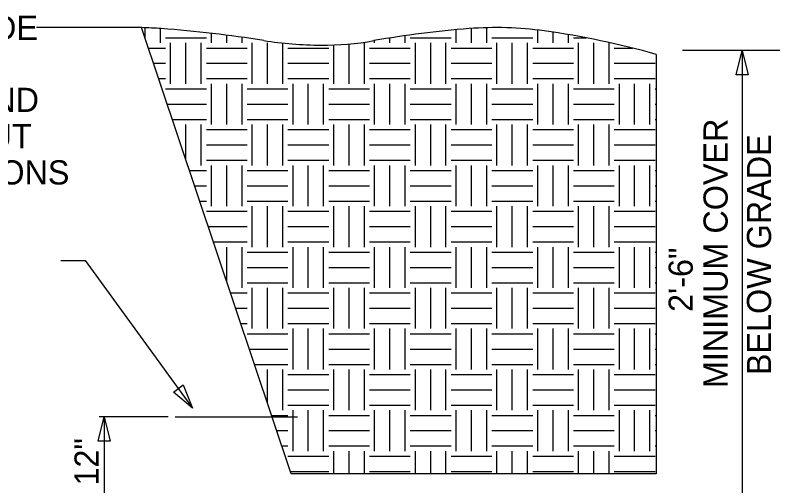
# Model space of a CAD drawing. Extents: x -12315.1 to -12267.3, y -12275 to -12184.8.
# Drawn here: x -12288.43 to -12267.35, y -12197.77 to -12184.81 of the extents above; entities that cross this region are included whole.
import ezdxf

# ---------------------------------------------------------------- set-up
doc = ezdxf.new("R2010")
doc.units = 0
for name, color, linetype in [('G-ANNO-TEXT', 7, 'Continuous'), ('G-DETL-LINE', 7, 'Continuous'), ('G-DETL-PATT', 7, 'Continuous')]:
    doc.layers.add(name, color=color, linetype=linetype)

msp = doc.modelspace()

# ---------------------------------------------------------------- linework, layer by layer
at = {"layer": 'G-ANNO-TEXT'}
for p, q in [((-12284.948, -12185.147), (-12287.843, -12185.147)), ((-12270.031, -12185.766), (-12267.346, -12185.766)), ((-12268.379, -12185.78), (-12268.379, -12199.257)), ((-12287.171, -12191.568), (-12286.504, -12191.568)), ((-12286.504, -12191.568), (-12283.54, -12195.634)), ((-12284.216, -12195.878), (-12286.118, -12195.878)), ((-12285.975, -12195.878), (-12285.975, -12199.291))]:
    msp.add_line(p, q, dxfattribs=at)
for points in [[(-12268.545, -12186.447), (-12268.379, -12185.78), (-12268.212, -12186.447)], [(-12283.798, -12194.997), (-12283.54, -12195.634), (-12284.067, -12195.193)], [(-12286.141, -12196.545), (-12285.975, -12195.878), (-12285.808, -12196.545)]]:
    msp.add_lwpolyline(points, close=True, dxfattribs=at)
at = {"layer": 'G-DETL-LINE'}
for p, q in [((-12280.823, -12197.442), (-12284.948, -12185.147)), ((-12270.751, -12185.884), (-12270.751, -12197.442)), ((-12270.751, -12197.442), (-12280.823, -12197.442))]:
    msp.add_line(p, q, dxfattribs=at)
for centre, radius, start, end in [((-12285.272, -12197.103), 11.96, 85.8256, 88.4429), ((-12286.828, -12218.429), 33.343, 80.9379, 85.8263), ((-12273.898, -12211.649), 26.551, 94.3454, 100.0626), ((-12275.172, -12194.879), 9.733, 82.1646, 94.3457), ((-12276.956, -12207.838), 22.814, 74.2168, 82.1645), ((-12279.945, -12175.273), 10.358, 260.9379, 269.7145), ((-12279.956, -12177.511), 8.12, 269.7145, 280.0628)]:
    msp.add_arc(centre, radius, start, end, dxfattribs=at)
at = {"layer": 'G-DETL-PATT'}
for p, q in [((-12284.847, -12185.448), (-12284.847, -12185.15)), ((-12284.847, -12185.448), (-12284.847, -12185.15)), ((-12284.425, -12185.569), (-12284.425, -12185.172)), ((-12276.268, -12185.569), (-12276.268, -12185.203)), ((-12275.847, -12185.569), (-12275.847, -12185.169)), ((-12275.425, -12185.569), (-12275.425, -12185.149)), ((-12274.018, -12185.569), (-12274.018, -12185.214)), ((-12284.284, -12185.428), (-12283.159, -12185.428)), ((-12283.018, -12185.569), (-12283.018, -12185.304)), ((-12282.597, -12185.569), (-12282.597, -12185.355)), ((-12282.175, -12185.569), (-12282.175, -12185.412)), ((-12278.097, -12185.569), (-12278.097, -12185.431)), ((-12277.675, -12185.569), (-12277.675, -12185.367)), ((-12277.534, -12185.428), (-12276.409, -12185.428)), ((-12275.284, -12185.428), (-12274.159, -12185.428)), ((-12273.597, -12185.569), (-12273.597, -12185.272)), ((-12273.175, -12185.569), (-12273.175, -12185.339)), ((-12273.034, -12185.428), (-12272.679, -12185.428)), ((-12284.143, -12186.694), (-12284.143, -12185.569)), ((-12283.722, -12186.694), (-12283.722, -12185.569)), ((-12283.3, -12186.694), (-12283.3, -12185.569)), ((-12281.893, -12186.694), (-12281.893, -12185.569)), ((-12281.472, -12186.694), (-12281.472, -12185.569)), ((-12281.05, -12186.694), (-12281.05, -12185.572)), ((-12279.643, -12186.694), (-12279.643, -12185.625)), ((-12279.222, -12186.694), (-12279.222, -12185.597)), ((-12278.8, -12186.694), (-12278.8, -12185.569)), ((-12278.518, -12185.569), (-12278.518, -12185.502)), ((-12277.393, -12186.694), (-12277.393, -12185.569)), ((-12276.972, -12186.694), (-12276.972, -12185.569)), ((-12276.55, -12186.694), (-12276.55, -12185.569)), ((-12275.143, -12186.694), (-12275.143, -12185.569)), ((-12274.722, -12186.694), (-12274.722, -12185.569)), ((-12274.3, -12186.694), (-12274.3, -12185.569)), ((-12272.893, -12186.694), (-12272.893, -12185.569)), ((-12272.472, -12186.694), (-12272.472, -12185.569)), ((-12272.05, -12186.694), (-12272.05, -12185.569)), ((-12284.759, -12185.709), (-12284.284, -12185.709)), ((-12283.159, -12185.709), (-12282.034, -12185.709)), ((-12280.909, -12185.709), (-12279.784, -12185.709)), ((-12278.659, -12185.709), (-12277.534, -12185.709)), ((-12276.409, -12185.709), (-12275.284, -12185.709)), ((-12274.159, -12185.709), (-12273.034, -12185.709)), ((-12271.909, -12185.709), (-12271.405, -12185.709)), ((-12284.617, -12186.131), (-12284.284, -12186.131)), ((-12283.159, -12186.131), (-12282.034, -12186.131)), ((-12280.909, -12186.131), (-12279.784, -12186.131)), ((-12278.659, -12186.131), (-12277.534, -12186.131)), ((-12276.409, -12186.131), (-12275.284, -12186.131)), ((-12274.159, -12186.131), (-12273.034, -12186.131)), ((-12271.909, -12186.131), (-12270.784, -12186.131)), ((-12284.476, -12186.553), (-12284.284, -12186.553)), ((-12284.425, -12186.706), (-12284.425, -12186.694)), ((-12283.159, -12186.553), (-12282.034, -12186.553)), ((-12283.018, -12187.819), (-12283.018, -12186.694)), ((-12282.597, -12187.819), (-12282.597, -12186.694)), ((-12282.175, -12187.819), (-12282.175, -12186.694)), ((-12280.909, -12186.553), (-12279.784, -12186.553)), ((-12280.768, -12187.819), (-12280.768, -12186.694)), ((-12280.768, -12187.819), (-12280.768, -12186.694)), ((-12280.347, -12187.819), (-12280.347, -12186.694)), ((-12279.925, -12187.819), (-12279.925, -12186.694)), ((-12278.659, -12186.553), (-12277.534, -12186.553)), ((-12278.518, -12187.819), (-12278.518, -12186.694)), ((-12278.097, -12187.819), (-12278.097, -12186.694)), ((-12277.675, -12187.819), (-12277.675, -12186.694)), ((-12276.409, -12186.553), (-12275.284, -12186.553)), ((-12276.268, -12187.819), (-12276.268, -12186.694)), ((-12275.847, -12187.819), (-12275.847, -12186.694)), ((-12275.425, -12187.819), (-12275.425, -12186.694)), ((-12274.159, -12186.553), (-12273.034, -12186.553)), ((-12274.018, -12187.819), (-12274.018, -12186.694)), ((-12273.597, -12187.819), (-12273.597, -12186.694)), ((-12273.175, -12187.819), (-12273.175, -12186.694)), ((-12271.909, -12186.553), (-12270.784, -12186.553)), ((-12271.768, -12187.819), (-12271.768, -12186.694)), ((-12271.347, -12187.819), (-12271.347, -12186.694)), ((-12270.925, -12187.819), (-12270.925, -12186.694)), ((-12284.284, -12186.834), (-12283.159, -12186.834)), ((-12282.034, -12186.834), (-12280.909, -12186.834)), ((-12279.784, -12186.834), (-12278.659, -12186.834)), ((-12277.534, -12186.834), (-12276.409, -12186.834)), ((-12275.284, -12186.834), (-12274.159, -12186.834)), ((-12273.034, -12186.834), (-12271.909, -12186.834)), ((-12270.784, -12186.834), (-12270.751, -12186.834)), ((-12284.24, -12187.256), (-12283.159, -12187.256)), ((-12282.034, -12187.256), (-12280.909, -12187.256)), ((-12279.784, -12187.256), (-12278.659, -12187.256)), ((-12277.534, -12187.256), (-12276.409, -12187.256)), ((-12275.284, -12187.256), (-12274.159, -12187.256)), ((-12273.034, -12187.256), (-12271.909, -12187.256)), ((-12270.784, -12187.256), (-12270.751, -12187.256)), ((-12284.098, -12187.678), (-12283.159, -12187.678)), ((-12282.034, -12187.678), (-12280.909, -12187.678)), ((-12279.784, -12187.678), (-12278.659, -12187.678)), ((-12277.534, -12187.678), (-12276.409, -12187.678)), ((-12275.284, -12187.678), (-12274.159, -12187.678)), ((-12273.034, -12187.678), (-12271.909, -12187.678)), ((-12270.784, -12187.678), (-12270.751, -12187.678)), ((-12283.722, -12188.801), (-12283.722, -12187.819)), ((-12283.3, -12188.944), (-12283.3, -12187.819)), ((-12283.159, -12187.959), (-12282.034, -12187.959)), ((-12281.893, -12188.944), (-12281.893, -12187.819)), ((-12281.472, -12188.944), (-12281.472, -12187.819)), ((-12281.05, -12188.944), (-12281.05, -12187.819)), ((-12280.909, -12187.959), (-12279.784, -12187.959)), ((-12279.643, -12188.944), (-12279.643, -12187.819)), ((-12279.222, -12188.944), (-12279.222, -12187.819)), ((-12278.8, -12188.944), (-12278.8, -12187.819)), ((-12278.659, -12187.959), (-12277.534, -12187.959)), ((-12277.393, -12188.944), (-12277.393, -12187.819)), ((-12276.972, -12188.944), (-12276.972, -12187.819)), ((-12276.55, -12188.944), (-12276.55, -12187.819)), ((-12276.409, -12187.959), (-12275.284, -12187.959)), ((-12275.143, -12188.944), (-12275.143, -12187.819)), ((-12274.722, -12188.944), (-12274.722, -12187.819)), ((-12274.3, -12188.944), (-12274.3, -12187.819)), ((-12274.159, -12187.959), (-12273.034, -12187.959)), ((-12272.893, -12188.944), (-12272.893, -12187.819)), ((-12272.472, -12188.944), (-12272.472, -12187.819)), ((-12272.05, -12188.944), (-12272.05, -12187.819)), ((-12271.909, -12187.959), (-12270.784, -12187.959)), ((-12283.159, -12188.381), (-12282.034, -12188.381)), ((-12280.909, -12188.381), (-12279.784, -12188.381)), ((-12278.659, -12188.381), (-12277.534, -12188.381)), ((-12276.409, -12188.381), (-12275.284, -12188.381)), ((-12274.159, -12188.381), (-12273.034, -12188.381)), ((-12271.909, -12188.381), (-12270.784, -12188.381)), ((-12283.159, -12188.803), (-12282.034, -12188.803)), ((-12280.909, -12188.803), (-12279.784, -12188.803)), ((-12278.659, -12188.803), (-12277.534, -12188.803)), ((-12276.409, -12188.803), (-12275.284, -12188.803)), ((-12274.159, -12188.803), (-12273.034, -12188.803)), ((-12271.909, -12188.803), (-12270.784, -12188.803)), ((-12283.018, -12190.069), (-12283.018, -12188.944)), ((-12282.597, -12190.069), (-12282.597, -12188.944)), ((-12282.175, -12190.069), (-12282.175, -12188.944)), ((-12280.768, -12190.069), (-12280.768, -12188.944)), ((-12280.347, -12190.069), (-12280.347, -12188.944)), ((-12279.925, -12190.069), (-12279.925, -12188.944)), ((-12278.518, -12190.069), (-12278.518, -12188.944)), ((-12278.097, -12190.069), (-12278.097, -12188.944)), ((-12277.675, -12190.069), (-12277.675, -12188.944)), ((-12276.268, -12190.069), (-12276.268, -12188.944)), ((-12275.847, -12190.069), (-12275.847, -12188.944)), ((-12275.425, -12190.069), (-12275.425, -12188.944)), ((-12274.018, -12190.069), (-12274.018, -12188.944)), ((-12273.597, -12190.069), (-12273.597, -12188.944)), ((-12273.175, -12190.069), (-12273.175, -12188.944)), ((-12271.768, -12190.069), (-12271.768, -12188.944)), ((-12271.347, -12190.069), (-12271.347, -12188.944)), ((-12270.925, -12190.069), (-12270.925, -12188.944)), ((-12283.627, -12189.084), (-12283.159, -12189.084)), ((-12282.034, -12189.084), (-12280.909, -12189.084)), ((-12279.784, -12189.084), (-12278.659, -12189.084)), ((-12277.534, -12189.084), (-12276.409, -12189.084)), ((-12275.284, -12189.084), (-12274.159, -12189.084)), ((-12273.034, -12189.084), (-12271.909, -12189.084)), ((-12270.784, -12189.084), (-12270.751, -12189.084)), ((-12283.485, -12189.506), (-12283.159, -12189.506)), ((-12282.034, -12189.506), (-12280.909, -12189.506)), ((-12279.784, -12189.506), (-12278.659, -12189.506)), ((-12277.534, -12189.506), (-12276.409, -12189.506)), ((-12275.284, -12189.506), (-12274.159, -12189.506)), ((-12273.034, -12189.506), (-12271.909, -12189.506)), ((-12270.784, -12189.506), (-12270.751, -12189.506)), ((-12283.344, -12189.928), (-12283.159, -12189.928)), ((-12282.034, -12189.928), (-12280.909, -12189.928)), ((-12281.893, -12191.194), (-12281.893, -12190.069)), ((-12281.472, -12191.194), (-12281.472, -12190.069)), ((-12281.05, -12191.194), (-12281.05, -12190.069)), ((-12279.784, -12189.928), (-12278.659, -12189.928)), ((-12279.643, -12191.194), (-12279.643, -12190.069)), ((-12279.222, -12191.194), (-12279.222, -12190.069)), ((-12278.8, -12191.194), (-12278.8, -12190.069)), ((-12277.534, -12189.928), (-12276.409, -12189.928)), ((-12277.393, -12191.194), (-12277.393, -12190.069)), ((-12276.972, -12191.194), (-12276.972, -12190.069)), ((-12276.55, -12191.194), (-12276.55, -12190.069)), ((-12275.284, -12189.928), (-12274.159, -12189.928)), ((-12275.143, -12191.194), (-12275.143, -12190.069)), ((-12274.722, -12191.194), (-12274.722, -12190.069)), ((-12274.3, -12191.194), (-12274.3, -12190.069)), ((-12273.034, -12189.928), (-12271.909, -12189.928)), ((-12272.893, -12191.194), (-12272.893, -12190.069)), ((-12272.472, -12191.194), (-12272.472, -12190.069)), ((-12272.05, -12191.194), (-12272.05, -12190.069)), ((-12270.784, -12189.928), (-12270.751, -12189.928)), ((-12283.159, -12190.209), (-12282.034, -12190.209)), ((-12280.909, -12190.209), (-12279.784, -12190.209)), ((-12278.659, -12190.209), (-12277.534, -12190.209)), ((-12276.409, -12190.209), (-12275.284, -12190.209)), ((-12274.159, -12190.209), (-12273.034, -12190.209)), ((-12271.909, -12190.209), (-12270.784, -12190.209)), ((-12271.909, -12190.209), (-12270.784, -12190.209)), ((-12283.108, -12190.631), (-12282.034, -12190.631)), ((-12283.108, -12190.631), (-12282.034, -12190.631)), ((-12280.909, -12190.631), (-12279.784, -12190.631)), ((-12278.659, -12190.631), (-12277.534, -12190.631)), ((-12276.409, -12190.631), (-12275.284, -12190.631)), ((-12274.159, -12190.631), (-12273.034, -12190.631)), ((-12271.909, -12190.631), (-12270.784, -12190.631)), ((-12282.966, -12191.053), (-12282.034, -12191.053)), ((-12280.909, -12191.053), (-12279.784, -12191.053)), ((-12278.659, -12191.053), (-12277.534, -12191.053)), ((-12276.409, -12191.053), (-12275.284, -12191.053)), ((-12274.159, -12191.053), (-12273.034, -12191.053)), ((-12271.909, -12191.053), (-12270.784, -12191.053)), ((-12282.597, -12192.155), (-12282.597, -12191.194)), ((-12282.175, -12192.319), (-12282.175, -12191.194)), ((-12282.034, -12191.334), (-12280.909, -12191.334)), ((-12280.768, -12192.319), (-12280.768, -12191.194)), ((-12280.347, -12192.319), (-12280.347, -12191.194)), ((-12279.925, -12192.319), (-12279.925, -12191.194)), ((-12279.784, -12191.334), (-12278.659, -12191.334)), ((-12278.518, -12192.319), (-12278.518, -12191.194)), ((-12278.097, -12192.319), (-12278.097, -12191.194)), ((-12277.675, -12192.319), (-12277.675, -12191.194)), ((-12277.534, -12191.334), (-12276.409, -12191.334)), ((-12276.268, -12192.319), (-12276.268, -12191.194)), ((-12275.847, -12192.319), (-12275.847, -12191.194)), ((-12275.425, -12192.319), (-12275.425, -12191.194)), ((-12275.284, -12191.334), (-12274.159, -12191.334)), ((-12274.018, -12192.319), (-12274.018, -12191.194)), ((-12273.597, -12192.319), (-12273.597, -12191.194)), ((-12273.175, -12192.319), (-12273.175, -12191.194)), ((-12273.034, -12191.334), (-12271.909, -12191.334)), ((-12271.768, -12192.319), (-12271.768, -12191.194)), ((-12271.347, -12192.319), (-12271.347, -12191.194)), ((-12270.925, -12192.319), (-12270.925, -12191.194)), ((-12270.784, -12191.334), (-12270.751, -12191.334)), ((-12282.034, -12191.756), (-12280.909, -12191.756)), ((-12279.784, -12191.756), (-12278.659, -12191.756)), ((-12277.534, -12191.756), (-12276.409, -12191.756)), ((-12275.284, -12191.756), (-12274.159, -12191.756)), ((-12273.034, -12191.756), (-12271.909, -12191.756)), ((-12270.784, -12191.756), (-12270.751, -12191.756)), ((-12282.034, -12192.178), (-12280.909, -12192.178)), ((-12279.784, -12192.178), (-12278.659, -12192.178)), ((-12277.534, -12192.178), (-12276.409, -12192.178)), ((-12275.284, -12192.178), (-12274.159, -12192.178)), ((-12273.034, -12192.178), (-12271.909, -12192.178)), ((-12270.784, -12192.178), (-12270.751, -12192.178)), ((-12281.893, -12193.444), (-12281.893, -12192.319)), ((-12281.472, -12193.444), (-12281.472, -12192.319)), ((-12281.05, -12193.444), (-12281.05, -12192.319)), ((-12279.643, -12193.444), (-12279.643, -12192.319)), ((-12279.222, -12193.444), (-12279.222, -12192.319)), ((-12278.8, -12193.444), (-12278.8, -12192.319)), ((-12277.393, -12193.444), (-12277.393, -12192.319)), ((-12276.972, -12193.444), (-12276.972, -12192.319)), ((-12276.55, -12193.444), (-12276.55, -12192.319)), ((-12275.143, -12193.444), (-12275.143, -12192.319)), ((-12274.722, -12193.444), (-12274.722, -12192.319)), ((-12274.3, -12193.444), (-12274.3, -12192.319)), ((-12272.893, -12193.444), (-12272.893, -12192.319)), ((-12272.472, -12193.444), (-12272.472, -12192.319)), ((-12272.05, -12193.444), (-12272.05, -12192.319)), ((-12282.494, -12192.459), (-12282.034, -12192.459)), ((-12280.909, -12192.459), (-12279.784, -12192.459)), ((-12278.659, -12192.459), (-12277.534, -12192.459)), ((-12276.409, -12192.459), (-12275.284, -12192.459)), ((-12274.159, -12192.459), (-12273.034, -12192.459)), ((-12271.909, -12192.459), (-12270.784, -12192.459)), ((-12282.353, -12192.881), (-12282.034, -12192.881)), ((-12280.909, -12192.881), (-12279.784, -12192.881)), ((-12278.659, -12192.881), (-12277.534, -12192.881)), ((-12276.409, -12192.881), (-12275.284, -12192.881)), ((-12274.159, -12192.881), (-12273.034, -12192.881)), ((-12271.909, -12192.881), (-12270.784, -12192.881)), ((-12282.211, -12193.303), (-12282.034, -12193.303)), ((-12280.909, -12193.303), (-12279.784, -12193.303)), ((-12280.768, -12194.569), (-12280.768, -12193.444)), ((-12280.347, -12194.569), (-12280.347, -12193.444)), ((-12279.925, -12194.569), (-12279.925, -12193.444)), ((-12278.659, -12193.303), (-12277.534, -12193.303)), ((-12278.518, -12194.569), (-12278.518, -12193.444)), ((-12278.097, -12194.569), (-12278.097, -12193.444)), ((-12277.675, -12194.569), (-12277.675, -12193.444)), ((-12276.409, -12193.303), (-12275.284, -12193.303)), ((-12276.268, -12194.569), (-12276.268, -12193.444)), ((-12275.847, -12194.569), (-12275.847, -12193.444)), ((-12275.425, -12194.569), (-12275.425, -12193.444)), ((-12274.159, -12193.303), (-12273.034, -12193.303)), ((-12274.018, -12194.569), (-12274.018, -12193.444)), ((-12273.597, -12194.569), (-12273.597, -12193.444)), ((-12273.175, -12194.569), (-12273.175, -12193.444)), ((-12271.909, -12193.303), (-12270.784, -12193.303)), ((-12271.768, -12194.569), (-12271.768, -12193.444)), ((-12271.347, -12194.569), (-12271.347, -12193.444)), ((-12270.925, -12194.569), (-12270.925, -12193.444)), ((-12282.034, -12193.584), (-12280.909, -12193.584)), ((-12279.784, -12193.584), (-12278.659, -12193.584)), ((-12277.534, -12193.584), (-12276.409, -12193.584)), ((-12275.284, -12193.584), (-12274.159, -12193.584)), ((-12273.034, -12193.584), (-12271.909, -12193.584)), ((-12270.784, -12193.584), (-12270.751, -12193.584)), ((-12281.975, -12194.006), (-12280.909, -12194.006)), ((-12279.784, -12194.006), (-12278.659, -12194.006)), ((-12277.534, -12194.006), (-12276.409, -12194.006)), ((-12275.284, -12194.006), (-12274.159, -12194.006)), ((-12273.034, -12194.006), (-12271.909, -12194.006)), ((-12270.784, -12194.006), (-12270.751, -12194.006)), ((-12281.834, -12194.428), (-12280.909, -12194.428)), ((-12279.784, -12194.428), (-12278.659, -12194.428)), ((-12277.534, -12194.428), (-12276.409, -12194.428)), ((-12275.284, -12194.428), (-12274.159, -12194.428)), ((-12273.034, -12194.428), (-12271.909, -12194.428)), ((-12270.784, -12194.428), (-12270.751, -12194.428)), ((-12281.472, -12195.508), (-12281.472, -12194.569)), ((-12281.05, -12195.694), (-12281.05, -12194.569)), ((-12280.909, -12194.709), (-12279.784, -12194.709)), ((-12279.643, -12195.694), (-12279.643, -12194.569)), ((-12279.222, -12195.694), (-12279.222, -12194.569)), ((-12278.8, -12195.694), (-12278.8, -12194.569)), ((-12278.659, -12194.709), (-12277.534, -12194.709)), ((-12277.393, -12195.694), (-12277.393, -12194.569)), ((-12276.972, -12195.694), (-12276.972, -12194.569)), ((-12276.55, -12195.694), (-12276.55, -12194.569)), ((-12276.409, -12194.709), (-12275.284, -12194.709)), ((-12275.143, -12195.694), (-12275.143, -12194.569)), ((-12274.722, -12195.694), (-12274.722, -12194.569)), ((-12274.3, -12195.694), (-12274.3, -12194.569)), ((-12274.159, -12194.709), (-12273.034, -12194.709)), ((-12272.893, -12195.694), (-12272.893, -12194.569)), ((-12272.472, -12195.694), (-12272.472, -12194.569)), ((-12272.05, -12195.694), (-12272.05, -12194.569)), ((-12271.909, -12194.709), (-12270.784, -12194.709)), ((-12280.909, -12195.131), (-12279.784, -12195.131)), ((-12278.659, -12195.131), (-12277.534, -12195.131)), ((-12276.409, -12195.131), (-12275.284, -12195.131)), ((-12274.159, -12195.131), (-12273.034, -12195.131)), ((-12271.909, -12195.131), (-12270.784, -12195.131)), ((-12280.909, -12195.553), (-12279.784, -12195.553)), ((-12280.768, -12196.819), (-12280.768, -12195.694)), ((-12280.347, -12196.819), (-12280.347, -12195.694)), ((-12279.925, -12196.819), (-12279.925, -12195.694)), ((-12278.659, -12195.553), (-12277.534, -12195.553)), ((-12278.518, -12196.819), (-12278.518, -12195.694)), ((-12278.097, -12196.819), (-12278.097, -12195.694)), ((-12277.675, -12196.819), (-12277.675, -12195.694)), ((-12276.409, -12195.553), (-12275.284, -12195.553)), ((-12276.268, -12196.819), (-12276.268, -12195.694)), ((-12275.847, -12196.819), (-12275.847, -12195.694)), ((-12275.425, -12196.819), (-12275.425, -12195.694)), ((-12275.425, -12196.819), (-12275.425, -12195.694)), ((-12274.159, -12195.553), (-12273.034, -12195.553)), ((-12274.018, -12196.819), (-12274.018, -12195.694)), ((-12273.597, -12196.819), (-12273.597, -12195.694)), ((-12273.175, -12196.819), (-12273.175, -12195.694)), ((-12271.909, -12195.553), (-12270.784, -12195.553)), ((-12271.768, -12196.819), (-12271.768, -12195.694)), ((-12271.347, -12196.819), (-12271.347, -12195.694)), ((-12270.925, -12196.819), (-12270.925, -12195.694)), ((-12284.023, -12195.878), (-12280.648, -12195.878)), ((-12281.362, -12195.834), (-12280.909, -12195.834)), ((-12279.784, -12195.834), (-12278.659, -12195.834)), ((-12277.534, -12195.834), (-12276.409, -12195.834)), ((-12275.284, -12195.834), (-12274.159, -12195.834)), ((-12273.034, -12195.834), (-12271.909, -12195.834)), ((-12270.784, -12195.834), (-12270.751, -12195.834)), ((-12281.221, -12196.256), (-12280.909, -12196.256)), ((-12279.784, -12196.256), (-12278.659, -12196.256)), ((-12277.534, -12196.256), (-12276.409, -12196.256)), ((-12275.284, -12196.256), (-12274.159, -12196.256)), ((-12273.034, -12196.256), (-12271.909, -12196.256)), ((-12270.784, -12196.256), (-12270.751, -12196.256)), ((-12281.079, -12196.678), (-12280.909, -12196.678)), ((-12279.784, -12196.678), (-12278.659, -12196.678)), ((-12277.534, -12196.678), (-12276.409, -12196.678)), ((-12275.284, -12196.678), (-12274.159, -12196.678)), ((-12273.034, -12196.678), (-12271.909, -12196.678)), ((-12270.784, -12196.678), (-12270.751, -12196.678)), ((-12280.909, -12196.959), (-12279.784, -12196.959)), ((-12279.643, -12197.441), (-12279.643, -12196.819)), ((-12279.222, -12197.441), (-12279.222, -12196.819)), ((-12278.8, -12197.441), (-12278.8, -12196.819)), ((-12278.659, -12196.959), (-12277.534, -12196.959)), ((-12277.393, -12197.441), (-12277.393, -12196.819)), ((-12276.972, -12197.441), (-12276.972, -12196.819)), ((-12276.55, -12197.441), (-12276.55, -12196.819)), ((-12276.409, -12196.959), (-12275.284, -12196.959)), ((-12275.143, -12197.441), (-12275.143, -12196.819)), ((-12274.722, -12197.441), (-12274.722, -12196.819)), ((-12274.3, -12197.441), (-12274.3, -12196.819)), ((-12274.159, -12196.959), (-12273.034, -12196.959)), ((-12272.893, -12197.441), (-12272.893, -12196.819)), ((-12272.472, -12197.441), (-12272.472, -12196.819)), ((-12272.05, -12197.441), (-12272.05, -12196.819)), ((-12271.909, -12196.959), (-12270.784, -12196.959)), ((-12280.843, -12197.381), (-12279.784, -12197.381)), ((-12278.659, -12197.381), (-12277.534, -12197.381)), ((-12276.409, -12197.381), (-12275.284, -12197.381)), ((-12274.159, -12197.381), (-12273.034, -12197.381)), ((-12271.909, -12197.381), (-12270.784, -12197.381))]:
    msp.add_line(p, q, dxfattribs=at)

# ---------------------------------------------------------------- texts
at = {"layer": 'G-ANNO-TEXT'}
for s, height, p in [('GRADE', 0.6667, (-12290.975, -12185.484)), ('#4/0 BARE COPPER GROUND', 0.66667, (-12300.408, -12187.471)), ('CONDUCTOR THROUGHOUT', 0.66667, (-12300.408, -12188.471)), ('DUCT TYP. FOR ALL SECTIONS', 0.66667, (-12300.408, -12189.471))]:
    msp.add_text(s, height=height, dxfattribs=at).set_placement(p)
for s, height, p in [('MINIMUM COVER', 0.66667, (-12268.781, -12195.083)), ('BELOW GRADE', 0.66667, (-12267.583, -12194.725)), ('2\'-6" ', 0.6667, (-12269.743, -12192.984)), ('12"', 0.6667, (-12286.129, -12197.769))]:
    msp.add_text(s, height=height, rotation=90, dxfattribs=at).set_placement(p)

doc.saveas('drawing.dxf')
